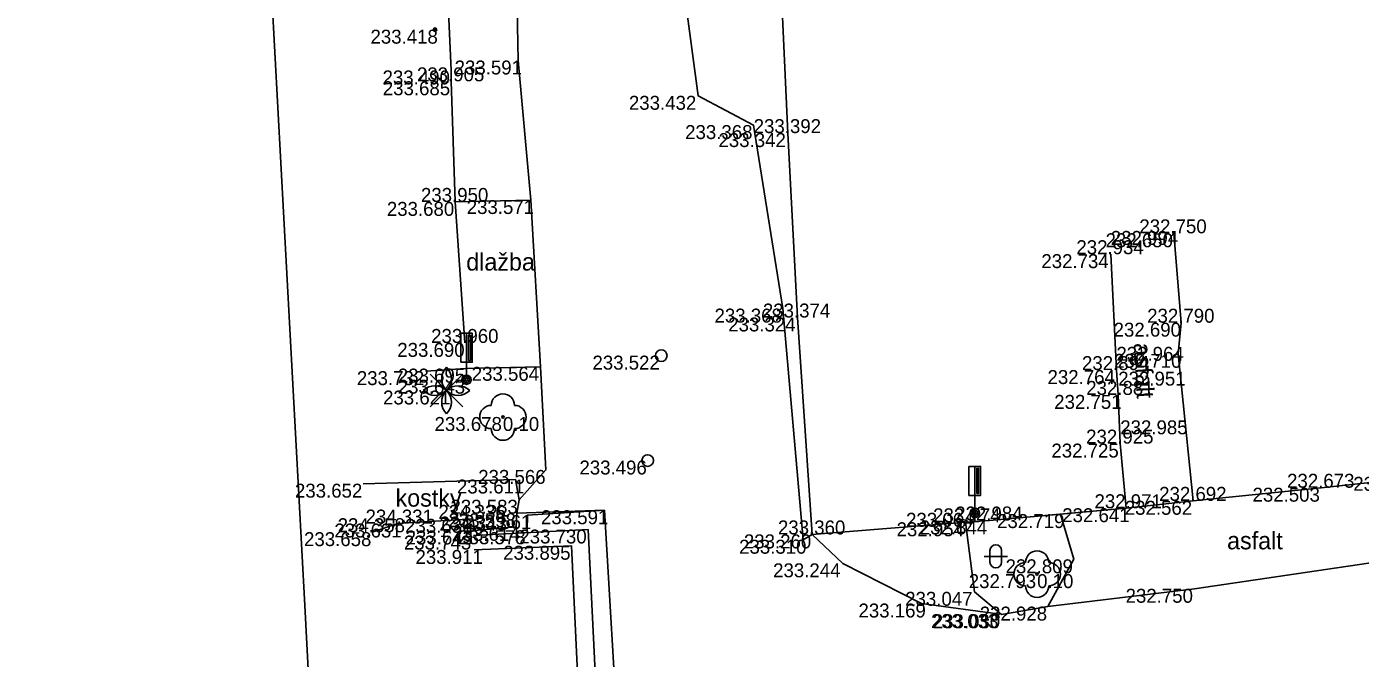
# Model space of a CAD drawing. Extents: x -599516 to -599132, y -1163668 to -1163119.
# Drawn here: x -599497.95 to -599469.23, y -1163503.15 to -1163489.55 of the extents above; entities that cross this region are included whole.
import ezdxf

# ---------------------------------------------------------------- set-up
doc = ezdxf.new("R2010")
doc.units = 0
for name, color, linetype in [('_ZEMERENI OBLAST', 7, 'Continuous'), ('Bod-oznac1', 7, 'Continuous'), ('Bod-oznac2', 7, 'Continuous'), ('Bod-oznac3', 7, 'Continuous'), ('Bod-vyska1', 7, 'Continuous'), ('Bod-vyska2', 7, 'Continuous'), ('Bod-vyska3', 7, 'Continuous'), ('Z_cela-hrobu-dolni-linie', 7, 'Continuous'), ('Z_cela-hrobu-horni-linie', 7, 'Continuous'), ('Z_chodnik', 7, 'Continuous'), ('Z_komunikace', 7, 'Continuous'), ('Z_kultury-znacky', 7, 'Continuous'), ('Z_nove-stromy-prumer-kmene', 7, 'Continuous'), ('Z_popis-budov-povrchu', 7, 'Continuous'), ('Z_povrchy-rozhrani-typu', 7, 'Continuous'), ('Z_schodiste', 7, 'Continuous'), ('Z_stromy-kere', 7, 'Continuous'), ('Z_stromy-nove-vysazene', 7, 'Continuous'), ('Z_voda-znacky-soupe', 7, 'Continuous'), ('Z_vol-zn-podrobny-vyskovy-bod-geo', 7, 'Continuous'), ('Z_zdi', 7, 'Continuous'), ('Z_znacky-ostatni-orientacni-sloupek', 7, 'Continuous'), ('Z_zpevnene-plochy', 7, 'Continuous')]:
    doc.layers.add(name, color=color, linetype=linetype)

msp = doc.modelspace()

# ---------------------------------------------------------------- linework, layer by layer
at = {"layer": '_ZEMERENI OBLAST'}
msp.add_lwpolyline([(-599497.946, -1163390.674), (-599491.96, -1163502.01), (-599489.976, -1163538.978), (-599287.834, -1163513.31), (-599283.12, -1163600.69), (-599345.275, -1163603.707), (-599342.31, -1163660.29), (-599277.306, -1163657.294), (-599220.632, -1163654.171)], dxfattribs=at)
at = {"layer": 'Bod-oznac1'}
for p, q in [((-599489.154, -1163489.618), (-599489.154, -1163489.618)), ((-599487.365, -1163490.281), (-599487.365, -1163490.281)), ((-599488.808, -1163490.728), (-599488.808, -1163490.728)), ((-599488.803, -1163490.495), (-599488.803, -1163490.495)), ((-599483.485, -1163491.041), (-599483.485, -1163491.041)), ((-599482.298, -1163491.671), (-599482.298, -1163491.671)), ((-599481.557, -1163491.843), (-599481.557, -1163491.843)), ((-599488.722, -1163493.324), (-599488.722, -1163493.324)), ((-599487.092, -1163493.284), (-599487.092, -1163493.284)), ((-599473.247, -1163494), (-599473.247, -1163494)), ((-599474.603, -1163494.449), (-599474.603, -1163494.449)), ((-599481.665, -1163495.621), (-599481.665, -1163495.621)), ((-599481.347, -1163495.812), (-599481.347, -1163495.812)), ((-599473.085, -1163495.924), (-599473.085, -1163495.924)), ((-599488.509, -1163496.359), (-599488.509, -1163496.359)), ((-599484.282, -1163496.633), (-599484.282, -1163496.633)), ((-599473.154, -1163496.595), (-599473.154, -1163496.595)), ((-599489.354, -1163496.967), (-599489.354, -1163496.967)), ((-599488.495, -1163496.912), (-599488.495, -1163496.912)), ((-599486.881, -1163496.874), (-599486.881, -1163496.874)), ((-599474.482, -1163496.944), (-599474.482, -1163496.944)), ((-599488.475, -1163497.151), (-599488.475, -1163497.151)), ((-599488.906, -1163497.384), (-599488.906, -1163497.384)), ((-599474.442, -1163497.478), (-599474.442, -1163497.478)), ((-599487.692, -1163497.954), (-599487.692, -1163497.954)), ((-599474.399, -1163498.526), (-599474.399, -1163498.526)), ((-599484.574, -1163498.891), (-599484.574, -1163498.891)), ((-599487.419, -1163499.3), (-599487.419, -1163499.3)), ((-599486.764, -1163499.093), (-599486.764, -1163499.093)), ((-599490.699, -1163499.389), (-599490.699, -1163499.389)), ((-599470.071, -1163499.476), (-599470.071, -1163499.476)), ((-599487.339, -1163499.735), (-599487.339, -1163499.735)), ((-599474.27, -1163499.917), (-599474.27, -1163499.917)), ((-599472.832, -1163499.758), (-599472.832, -1163499.758)), ((-599488.339, -1163500.146), (-599488.339, -1163500.146)), ((-599487.392, -1163500.026), (-599487.392, -1163500.026)), ((-599487.163, -1163500.065), (-599487.163, -1163500.065)), ((-599485.506, -1163499.961), (-599485.506, -1163499.961)), ((-599477.531, -1163500.016), (-599477.531, -1163500.016)), ((-599477.212, -1163500.181), (-599477.212, -1163500.181)), ((-599475.683, -1163500.044), (-599475.683, -1163500.044)), ((-599490.504, -1163500.433), (-599490.504, -1163500.433)), ((-599489.955, -1163500.247), (-599489.955, -1163500.247)), ((-599488.305, -1163500.397), (-599488.305, -1163500.397)), ((-599487.404, -1163500.32), (-599487.404, -1163500.32)), ((-599487.17, -1163500.392), (-599487.17, -1163500.392)), ((-599485.857, -1163500.376), (-599485.857, -1163500.376)), ((-599481.035, -1163500.481), (-599481.035, -1163500.481)), ((-599477.733, -1163500.22), (-599477.733, -1163500.22)), ((-599488.328, -1163500.506), (-599488.328, -1163500.506)), ((-599486.216, -1163500.725), (-599486.216, -1163500.725)), ((-599481.23, -1163500.596), (-599481.23, -1163500.596)), ((-599488.312, -1163500.816), (-599488.312, -1163500.816)), ((-599475.4, -1163501.017), (-599475.4, -1163501.017)), ((-599480.37, -1163501.104), (-599480.37, -1163501.104)), ((-599476.189, -1163501.336), (-599476.189, -1163501.336)), ((-599472.803, -1163501.652), (-599472.803, -1163501.652)), ((-599477.537, -1163501.717), (-599477.537, -1163501.717)), ((-599478.681, -1163501.969), (-599478.681, -1163501.969)), ((-599476.993, -1163502.196), (-599476.993, -1163502.196)), ((-599476.958, -1163502.201), (-599476.958, -1163502.201)), ((-599475.955, -1163502.035), (-599475.955, -1163502.035))]:
    msp.add_line(p, q, dxfattribs=at)
at = {"layer": 'Bod-oznac2'}
for p, q in [((-599488.808, -1163490.728), (-599488.808, -1163490.728)), ((-599481.557, -1163491.843), (-599481.557, -1163491.843)), ((-599488.722, -1163493.324), (-599488.722, -1163493.324)), ((-599473.247, -1163494), (-599473.247, -1163494)), ((-599474.603, -1163494.449), (-599474.603, -1163494.449)), ((-599481.347, -1163495.812), (-599481.347, -1163495.812)), ((-599473.085, -1163495.924), (-599473.085, -1163495.924)), ((-599488.509, -1163496.359), (-599488.509, -1163496.359)), ((-599474.482, -1163496.944), (-599474.482, -1163496.944)), ((-599474.442, -1163497.478), (-599474.442, -1163497.478)), ((-599474.399, -1163498.526), (-599474.399, -1163498.526)), ((-599470.071, -1163499.476), (-599470.071, -1163499.476)), ((-599474.27, -1163499.917), (-599474.27, -1163499.917)), ((-599472.832, -1163499.758), (-599472.832, -1163499.758)), ((-599488.339, -1163500.146), (-599488.339, -1163500.146)), ((-599477.212, -1163500.181), (-599477.212, -1163500.181)), ((-599490.504, -1163500.433), (-599490.504, -1163500.433)), ((-599489.955, -1163500.247), (-599489.955, -1163500.247)), ((-599488.305, -1163500.397), (-599488.305, -1163500.397)), ((-599481.035, -1163500.481), (-599481.035, -1163500.481)), ((-599477.733, -1163500.22), (-599477.733, -1163500.22))]:
    msp.add_line(p, q, dxfattribs=at)
at = {"layer": 'Bod-oznac3'}
for p, q in [((-599474.603, -1163494.449), (-599474.603, -1163494.449)), ((-599474.482, -1163496.944), (-599474.482, -1163496.944)), ((-599474.442, -1163497.478), (-599474.442, -1163497.478)), ((-599474.399, -1163498.526), (-599474.399, -1163498.526))]:
    msp.add_line(p, q, dxfattribs=at)
at = {"layer": 'Z_cela-hrobu-dolni-linie'}
msp.add_line((-599488.938, -1163487.535), (-599488.803, -1163490.495), dxfattribs=at)
for points in [[(-599482.36, -1163476.167), (-599482.238, -1163478.495), (-599482.159, -1163480.435), (-599482.132, -1163481.588), (-599482.047, -1163483.558), (-599481.993, -1163484.289), (-599481.898, -1163485.585), (-599481.776, -1163486.986), (-599481.557, -1163491.843), (-599481.347, -1163495.812), (-599481.035, -1163500.481)], [(-599488.509, -1163496.359), (-599488.722, -1163493.324), (-599488.808, -1163490.728), (-599488.803, -1163490.495)]]:
    msp.add_lwpolyline(points, dxfattribs=at)
at = {"layer": 'Z_cela-hrobu-horni-linie'}
for p, q in [((-599473.085, -1163495.924), (-599473.247, -1163494)), ((-599481.035, -1163500.481), (-599477.733, -1163500.22))]:
    msp.add_line(p, q, dxfattribs=at)
for points in [[(-599481.776, -1163486.986), (-599481.557, -1163491.843), (-599481.347, -1163495.812), (-599481.035, -1163500.481)], [(-599488.509, -1163496.359), (-599488.722, -1163493.324), (-599488.808, -1163490.728)], [(-599473.154, -1163496.595), (-599472.832, -1163499.758), (-599470.071, -1163499.476), (-599467.899, -1163499.242), (-599467.515, -1163499.203), (-599467.515, -1163499.203), (-599464.838, -1163498.918), (-599464.838, -1163498.918), (-599462.145, -1163498.622), (-599462.145, -1163498.622), (-599460.82, -1163498.447), (-599460.82, -1163498.447), (-599458.186, -1163498.179), (-599458.186, -1163498.179), (-599456.822, -1163498.026), (-599456.822, -1163498.026), (-599454.162, -1163497.728), (-599454.162, -1163497.728), (-599452.842, -1163497.557), (-599453.18, -1163494.392), (-599453.18, -1163494.392), (-599453.199, -1163494.077)], [(-599477.212, -1163500.181), (-599474.27, -1163499.917), (-599474.399, -1163498.526), (-599474.399, -1163498.526), (-599474.442, -1163497.478), (-599474.442, -1163497.478), (-599474.482, -1163496.944), (-599474.482, -1163496.944), (-599474.603, -1163494.449), (-599474.603, -1163494.449)]]:
    msp.add_lwpolyline(points, dxfattribs=at)
at = {"layer": 'Z_chodnik'}
for points in [[(-599473.247, -1163494), (-599473.085, -1163495.924), (-599473.154, -1163496.595), (-599472.832, -1163499.758)], [(-599474.27, -1163499.917), (-599474.399, -1163498.526), (-599474.442, -1163497.478), (-599474.482, -1163496.944), (-599474.603, -1163494.449)]]:
    msp.add_lwpolyline(points, dxfattribs=at)
at = {"layer": 'Z_komunikace'}
for p, q in [((-599477.733, -1163500.22), (-599477.212, -1163500.181)), ((-599477.212, -1163500.181), (-599477.212, -1163500.181)), ((-599481.23, -1163500.596), (-599481.035, -1163500.481)), ((-599481.035, -1163500.481), (-599477.733, -1163500.22))]:
    msp.add_line(p, q, dxfattribs=at)
for points in [[(-599484.151, -1163471.38), (-599484.056, -1163474.187), (-599484.044, -1163475.892), (-599484.779, -1163476.734), (-599485.227, -1163477.457), (-599485.206, -1163478.432), (-599483.614, -1163481.235), (-599483.443, -1163484.851), (-599483.458, -1163487.994), (-599483.733, -1163489.22), (-599483.485, -1163491.041), (-599482.298, -1163491.671), (-599481.665, -1163495.621), (-599481.23, -1163500.596)], [(-599486.881, -1163496.874), (-599487.092, -1163493.284), (-599487.365, -1163490.281), (-599487.423, -1163487.291), (-599487.645, -1163480.07), (-599487.841, -1163476.558)], [(-599485.506, -1163499.961), (-599487.392, -1163500.026), (-599487.339, -1163499.735), (-599486.764, -1163499.093), (-599486.881, -1163496.874)], [(-599477.212, -1163500.181), (-599475.683, -1163500.044), (-599474.27, -1163499.917), (-599472.832, -1163499.758), (-599470.071, -1163499.476), (-599467.899, -1163499.242)], [(-599485.506, -1163499.961), (-599485.193, -1163505.183), (-599484.949, -1163509.985)], [(-599475.955, -1163502.035), (-599475.4, -1163501.017), (-599475.683, -1163500.044)], [(-599477.733, -1163500.22), (-599477.537, -1163501.717), (-599476.958, -1163502.201)], [(-599476.958, -1163502.201), (-599475.955, -1163502.035)]]:
    msp.add_lwpolyline(points, dxfattribs=at)
at = {"layer": 'Z_kultury-znacky'}
for p, q in [((-599477.329, -1163500.953), (-599476.829, -1163500.953)), ((-599477.204, -1163500.828), (-599477.204, -1163501.078)), ((-599476.954, -1163500.828), (-599476.954, -1163501.078))]:
    msp.add_line(p, q, dxfattribs=at)
for centre, start, end in [((-599477.079, -1163500.828), 0, 180), ((-599477.079, -1163501.078), 180, 0)]:
    msp.add_arc(centre, 0.125, start, end, dxfattribs=at)
at = {"layer": 'Z_povrchy-rozhrani-typu'}
msp.add_line((-599481.035, -1163500.481), (-599480.37, -1163501.104), dxfattribs=at)
for points in [[(-599475.955, -1163502.035), (-599472.803, -1163501.652), (-599466.429, -1163500.713)], [(-599480.37, -1163501.104), (-599478.681, -1163501.969), (-599476.993, -1163502.196)]]:
    msp.add_lwpolyline(points, dxfattribs=at)
at = {"layer": 'Z_schodiste'}
for points in [[(-599487.17, -1163500.392), (-599487.163, -1163500.065), (-599485.506, -1163499.961)], [(-599487.812, -1163509.838), (-599485.4, -1163509.721), (-599485.857, -1163500.376), (-599488.328, -1163500.506)], [(-599488.312, -1163500.816), (-599486.216, -1163500.725), (-599485.806, -1163509.397), (-599487.826, -1163509.496)]]:
    msp.add_lwpolyline(points, dxfattribs=at)
at = {"layer": 'Z_stromy-kere'}
for p, q in [((-599488.552, -1163497.03), (-599489.26, -1163497.738)), ((-599489.26, -1163497.03), (-599488.552, -1163497.738)), ((-599488.552, -1163497.03), (-599489.26, -1163497.738)), ((-599489.26, -1163497.03), (-599488.552, -1163497.738)), ((-599488.552, -1163497.03), (-599489.26, -1163497.738)), ((-599489.26, -1163497.03), (-599488.552, -1163497.738))]:
    msp.add_line(p, q, dxfattribs=at)
for centre, start, end in [((-599489.156, -1163497.134), 225, 45), ((-599489.156, -1163497.134), 225, 45), ((-599489.156, -1163497.134), 225, 45), ((-599488.656, -1163497.134), 135, 315), ((-599488.656, -1163497.134), 135, 315), ((-599488.656, -1163497.134), 135, 315), ((-599489.156, -1163497.634), 315, 135), ((-599489.156, -1163497.634), 315, 135), ((-599489.156, -1163497.634), 315, 135), ((-599488.656, -1163497.634), 45, 225), ((-599488.656, -1163497.634), 45, 225), ((-599488.656, -1163497.634), 45, 225)]:
    msp.add_arc(centre, 0.354, start, end, dxfattribs=at)
at = {"layer": 'Z_stromy-nove-vysazene'}
for centre in [(-599487.692, -1163497.954), (-599476.189, -1163501.336)]:
    msp.add_circle(centre, 0.025, dxfattribs=at)
for centre, start, end in [((-599487.692, -1163497.704), 0, 180), ((-599487.942, -1163497.954), 90, 270), ((-599487.442, -1163497.954), 270, 90), ((-599487.692, -1163498.204), 180, 0), ((-599476.189, -1163501.086), 0, 180), ((-599476.439, -1163501.336), 90, 270), ((-599475.939, -1163501.336), 270, 90), ((-599476.189, -1163501.586), 180, 0)]:
    msp.add_arc(centre, 0.25, start, end, dxfattribs=at)
at = {"layer": 'Z_voda-znacky-soupe'}
for centre in [(-599484.282, -1163496.633), (-599484.574, -1163498.891)]:
    msp.add_circle(centre, 0.125, dxfattribs=at)
at = {"layer": 'Z_vol-zn-podrobny-vyskovy-bod-geo'}
for radius in [0.0375, 0.0125]:
    msp.add_circle((-599489.154, -1163489.618), radius, dxfattribs=at)
at = {"layer": 'Z_zdi'}
for p, q in [((-599488.339, -1163500.146), (-599488.339, -1163500.146)), ((-599490.504, -1163500.433), (-599490.504, -1163500.433)), ((-599489.955, -1163500.247), (-599489.955, -1163500.247)), ((-599488.305, -1163500.397), (-599488.305, -1163500.397))]:
    msp.add_line(p, q, dxfattribs=at)
msp.add_lwpolyline([(-599488.305, -1163500.397), (-599488.339, -1163500.146), (-599489.955, -1163500.247), (-599490.504, -1163500.433)], dxfattribs=at)
msp.add_lwpolyline([(-599488.305, -1163500.397), (-599488.339, -1163500.146), (-599489.955, -1163500.247), (-599490.504, -1163500.433)], dxfattribs=at)
at = {"layer": 'Z_znacky-ostatni-orientacni-sloupek'}
for p, q in [((-599488.6, -1163496.151), (-599488.6, -1163496.776)), ((-599488.6, -1163496.151), (-599488.475, -1163496.151)), ((-599488.6, -1163496.776), (-599488.475, -1163496.776)), ((-599488.475, -1163496.776), (-599488.475, -1163497.051)), ((-599477.656, -1163499.016), (-599477.656, -1163499.641)), ((-599477.656, -1163499.016), (-599477.531, -1163499.016)), ((-599477.656, -1163499.641), (-599477.531, -1163499.641)), ((-599477.531, -1163499.641), (-599477.531, -1163499.916))]:
    msp.add_line(p, q, dxfattribs=at)
for points in [[(-599488.475, -1163496.776), (-599488.35, -1163496.776), (-599488.35, -1163496.151), (-599488.475, -1163496.151)], [(-599488.432, -1163496.734), (-599488.392, -1163496.734), (-599488.392, -1163496.194), (-599488.432, -1163496.194)], [(-599477.531, -1163499.641), (-599477.406, -1163499.641), (-599477.406, -1163499.016), (-599477.531, -1163499.016)], [(-599477.488, -1163499.599), (-599477.449, -1163499.599), (-599477.449, -1163499.059), (-599477.488, -1163499.059)]]:
    msp.add_lwpolyline(points, close=True, dxfattribs=at)
for centre, radius in [((-599488.475, -1163497.151), 0.1), ((-599488.475, -1163497.151), 0.065), ((-599488.475, -1163497.151), 0.03), ((-599477.531, -1163500.016), 0.1), ((-599477.531, -1163500.016), 0.065), ((-599477.531, -1163500.016), 0.03)]:
    msp.add_circle(centre, radius, dxfattribs=at)
at = {"layer": 'Z_zpevnene-plochy'}
for points in [[(-599488.722, -1163493.324), (-599487.092, -1163493.284)], [(-599486.881, -1163496.874), (-599488.495, -1163496.912), (-599489.354, -1163496.967)], [(-599487.339, -1163499.735), (-599487.419, -1163499.3), (-599490.699, -1163499.389)], [(-599487.392, -1163500.026), (-599487.404, -1163500.32), (-599488.305, -1163500.397)]]:
    msp.add_lwpolyline(points, dxfattribs=at)

# ---------------------------------------------------------------- texts
at = {"layer": 'Bod-vyska1'}
for s, p in [('233.418', (-599490.543, -1163489.918)), ('233.591', (-599488.731, -1163490.581)), ('233.490', (-599490.283, -1163490.795)), ('233.685', (-599490.278, -1163491.028)), ('233.432', (-599484.978, -1163491.341)), ('233.368', (-599483.768, -1163491.971)), ('233.342', (-599483.05, -1163492.143)), ('233.680', (-599490.19, -1163493.624)), ('233.571', (-599488.471, -1163493.584)), ('232.650', (-599474.715, -1163494.3)), ('232.734', (-599476.098, -1163494.749)), ('233.368', (-599483.135, -1163495.921)), ('233.324', (-599482.84, -1163496.112)), ('232.690', (-599474.542, -1163496.224)), ('233.690', (-599489.966, -1163496.659)), ('233.522', (-599485.764, -1163496.933)), ('232.710', (-599474.532, -1163496.895)), ('233.732', (-599490.837, -1163497.267)), ('233.695', (-599489.954, -1163497.212)), ('233.564', (-599488.363, -1163497.174)), ('232.764', (-599475.965, -1163497.244)), ('233.643', (-599489.956, -1163497.451)), ('233.621', (-599490.272, -1163497.684)), ('232.751', (-599475.821, -1163497.778)), ('233.678', (-599489.164, -1163498.254)), ('232.725', (-599475.882, -1163498.826)), ('233.496', (-599486.044, -1163499.191)), ('233.611', (-599488.681, -1163499.6)), ('233.566', (-599488.223, -1163499.393)), ('232.358', (-599469.381, -1163499.542)), ('233.652', (-599492.169, -1163499.689)), ('232.503', (-599471.551, -1163499.776)), ('233.583', (-599488.821, -1163500.035)), ('232.641', (-599475.648, -1163500.217)), ('232.562', (-599474.302, -1163500.058)), ('233.636', (-599489.798, -1163500.446)), ('233.598', (-599488.862, -1163500.326)), ('233.561', (-599488.529, -1163500.365)), ('233.591', (-599486.872, -1163500.261)), ('232.954', (-599479.215, -1163500.52)), ('233.064', (-599479.011, -1163500.316)), ('232.844', (-599478.716, -1163500.481)), ('232.719', (-599477.051, -1163500.344)), ('233.658', (-599491.974, -1163500.733)), ('233.631', (-599491.321, -1163500.547)), ('233.743', (-599489.823, -1163500.806)), ('233.643', (-599489.786, -1163500.697)), ('233.614', (-599488.782, -1163500.62)), ('233.578', (-599488.653, -1163500.692)), ('233.730', (-599487.338, -1163500.676)), ('233.260', (-599482.503, -1163500.781)), ('233.895', (-599487.686, -1163501.025)), ('233.310', (-599482.606, -1163500.896)), ('233.911', (-599489.574, -1163501.116)), ('232.809', (-599476.868, -1163501.317)), ('233.244', (-599481.874, -1163501.404)), ('232.793', (-599477.661, -1163501.636)), ('232.750', (-599474.284, -1163501.952)), ('233.047', (-599479.03, -1163502.017)), ('233.169', (-599480.036, -1163502.269)), ('233.033', (-599478.473, -1163502.496)), ('233.030', (-599478.436, -1163502.501)), ('232.928', (-599477.425, -1163502.335))]:
    msp.add_text(s, height=0.3, dxfattribs=at).set_placement(p)
at = {"layer": 'Bod-vyska2'}
for s, p in [('233.905', (-599489.542, -1163490.728)), ('233.392', (-599482.292, -1163491.843)), ('233.950', (-599489.456, -1163493.324)), ('232.750', (-599473.988, -1163494)), ('232.934', (-599475.344, -1163494.449)), ('233.374', (-599482.094, -1163495.812)), ('232.790', (-599473.82, -1163495.924)), ('233.960', (-599489.237, -1163496.359)), ('232.894', (-599475.223, -1163496.944)), ('232.881', (-599475.131, -1163497.478)), ('232.925', (-599475.134, -1163498.526)), ('232.673', (-599470.807, -1163499.476)), ('232.971', (-599474.954, -1163499.917)), ('232.692', (-599473.561, -1163499.758)), ('234.336', (-599489.08, -1163500.146)), ('233.174', (-599478.428, -1163500.22)), ('232.984', (-599477.953, -1163500.181)), ('234.358', (-599491.25, -1163500.433)), ('234.331', (-599490.649, -1163500.247)), ('234.343', (-599489.057, -1163500.397)), ('233.360', (-599481.769, -1163500.481))]:
    msp.add_text(s, height=0.3, dxfattribs=at).set_placement(p)
at = {"layer": 'Bod-vyska3'}
for s, p in [('232.994', (-599474.603, -1163494.249)), ('232.964', (-599474.482, -1163496.744)), ('232.951', (-599474.442, -1163497.278)), ('232.985', (-599474.399, -1163498.326))]:
    msp.add_text(s, height=0.3, dxfattribs=at).set_placement(p)
at = {"layer": 'Z_nove-stromy-prumer-kmene'}
for p in [(-599487.692, -1163498.254), (-599476.189, -1163501.636)]:
    msp.add_text('0.10', height=0.3, dxfattribs=at).set_placement(p)
at = {"layer": 'Z_popis-budov-povrchu'}
for s, p in [('dlažba', (-599488.481, -1163494.802)), ('kostky', (-599490.003, -1163499.883)), ('asfalt', (-599472.099, -1163500.802))]:
    msp.add_text(s, height=0.375, dxfattribs=at).set_placement(p)
msp.add_text('asfalt', height=0.375, rotation=273.4503, dxfattribs=at).set_placement((-599474.112, -1163496.368))

doc.saveas('drawing.dxf')
